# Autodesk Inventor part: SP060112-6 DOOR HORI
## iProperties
Created: 2012-06
Part Number: SP060112-6 DOOR HORI
Material: Aluminum-6061
Description: PROFILE 45X45 UL
Document SubType Name: Modeling
Designer: Administrator
Stock Number: 20.1063 PROFILE 45X45 UL
Density: 2.71 g/cm^3
FINISH: CLEAR ANODIZED
Author: Administrator
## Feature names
1. Extrusion1
2. Fillet1
